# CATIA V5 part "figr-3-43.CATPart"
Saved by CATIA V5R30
Part number: Part1
Bounding box of the stored display mesh (mm): x 0 to 0, y -151.508 to 68.716, z -53.883 to 66.715
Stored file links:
  D:\PROJECTS\CATIA V56R 2020\Resources\Parts File\c03_catia_v5_6r2020_prt\figr-3-43.CATPart
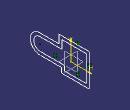
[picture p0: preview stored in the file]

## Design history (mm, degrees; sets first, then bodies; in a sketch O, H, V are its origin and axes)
Body1 (main body)
  Sketch1 on yz-plane, origin (0, 0, 0), H (0, 1, 0), V (0, 0, 1)
    point P1 (-23.9446, -41.7966)
    line L1 (-23.9446, -41.7966) -> (-23.9446, -23.995)
    line L2 (-23.9446, -23.995) -> (-115.8106, -23.995)
    arc A1 centre (-115.8106, -0.3669) radius 23.6281 from (-115.8106, -23.995) to (-115.8106, 23.2613) cw
    line L3 (-115.8106, 23.2613) -> (-33.6641, 23.2613)
    line L4 (-33.6641, 23.2613) -> (-33.6641, 54.6279)
    line L5 (-33.6641, 54.6279) -> (56.6292, 54.6279)
    line L6 (56.6292, 54.6279) -> (56.6292, -41.7966)
    line L7 (56.6292, -41.7966) -> (-23.9446, -41.7966)
    point P10 (-23.9446, -41.7966)
    line L8 (68.7159, 66.7146) -> (68.7159, -53.8833)
    line L9 (68.7159, -53.8833) -> (-36.0313, -53.8833)
    line L10 (-36.0313, -53.8833) -> (-36.0313, -36.0817)
    line L11 (-36.0313, -36.0817) -> (-115.8105, -36.0817)
    arc A2 centre (-115.8106, -0.3669) radius 35.7148 from (-115.8105, 35.348) to (-115.8105, -36.0817) ccw
    line L12 (-115.8105, 35.348) -> (-45.7508, 35.348)
    line L13 (-45.7508, 35.348) -> (-45.7508, 66.7146)
    line L14 (-45.7508, 66.7146) -> (68.7159, 66.7146)
    curve C1
    vertical: L1 V, L4 V, L6 V
    horizontal: L2 H, L5 H, L7 H
    tangency: A1 L2, L3 A1
    coincidence: P10 L1, P1 P10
